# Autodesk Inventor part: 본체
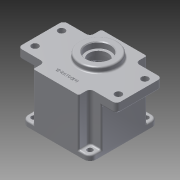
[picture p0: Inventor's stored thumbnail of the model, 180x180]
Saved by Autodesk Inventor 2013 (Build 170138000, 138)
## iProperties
Created: 2015-07
Part Number: 본체
Material: 알루미늄 6061
Document SubType Name: Modeling
Designer: user
Density: 2.71 g/cm^3
Mass: 705.922 g
Surface Area: 675.022 cm^2
Volume: 260.488 cm^3
Author: user
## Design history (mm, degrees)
sketch "스케치1"
  geometry: L1 (-37, 45)-(37, 45); L2 (45, 37)-(45, -37); L3 (37, -45)-(-37, -45); L4 (-45, -37)-(-45, 37); A1 r 8 centre (-37, 37) between (-37, 45) and (-45, 37); A2 r 8 centre (-37, -37) between (-45, -37) and (-37, -45); A3 r 8 centre (37, -37) between (37, -45) and (45, -37); A4 r 8 centre (37, 37) between (45, 37) and (37, 45); 6 further points
  constraints: 8 end point, 8 point on circle, 8 tangent, 6 point on line, 4 centre point, 3 equal radius, 2 midpoint, 2 parallel, 1 horizontal, 1 horizontal alignment, 1 perpendicular, 1 vertical alignment
  dimensions: "d0" = 90 distance of point (45, -45) point (-45, -45); "d1" = 90 distance of point (45, 45) point (45, -45); "d2" = 8 radius of A1
extrude "돌출1" new body sketch "스케치1" distance "d3" = 70; taper "d4" = 0 deg
sketch "스케치2"
  geometry: L1 (37, 45)-(-37, 45) reference; L2 (0, 45)-(0, 30); L3 (0, 30)-(60, 30); L4 (65, 25)-(65, -25); L5 (60, -30)-(-60, -30); L6 (-65, -25)-(-65, 25); L7 (-60, 30)-(0, 30); A1 r 5 centre (-60, 25) between (-60, 30) and (-65, 25); A2 r 5 centre (-60, -25) between (-65, -25) and (-60, -30); A3 r 5 centre (60, -25) between (60, -30) and (65, -25); A4 r 5 centre (60, 25) between (65, 25) and (60, 30); 5 further points
  constraints: 12 end point, 8 point on circle, 8 point on line, 8 tangent, 4 centre point, 4 perpendicular, 3 equal radius, 1 midpoint, 1 parallel
  dimensions: "d5" = 15 distance of L2.start L2.end; "d6" = 65 distance of L2.end point (65, 30); "d7" = 60 distance of point (65, 30) point (65, -30); "d8" = 130 distance of point (65, -30) point (-65, -30); "d9" = 60 distance of point (-65, -30) point (-65, 30); "d10" = 5 radius of A1
extrude "돌출2" join sketch "스케치2" distance "d11" = 12; taper "d12" = 0 deg
sketch "스케치3"
  geometry: L1 (-60, -30)-(-45, -30) reference; L2 (0, 0)-(0, 11); C1 r 25 at (0, 11)
  constraints: 2 end point, 1 centre point, 1 coincident, 1 perpendicular
  dimensions: "d13" = 11 distance of L2.start L2.end; "d14" = 25 radius of C1
extrude "돌출3" join sketch "스케치3" distance "d15" = 7; taper "d16" = 0 deg
sketch "스케치4"
  geometry: C1 r 25 at (0, 0) reference; C2 r 16 at (0, 0); 1 further point
  constraints: 1 centre point, 1 coincident
  dimensions: "d17" = 16 radius of C2
extrude "돌출4" cut sketch "스케치4" distance "d18" = 8; taper "d19" = 0 deg
sketch "스케치5"
  geometry: C1 r 16 at (0, 0) reference; C2 r 12.5 at (0, 0); 1 further point
  constraints: 1 centre point, 1 coincident
  dimensions: "d20" = 12.5 radius of C2
extrude "돌출5" cut sketch "스케치5" distance "d21" = 5; taper "d22" = 0 deg
sketch "스케치6"
  geometry: C1 r 12.5 at (0, 0) reference; C2 r 17.5 at (0, 0); 1 further point
  constraints: 1 centre point, 1 coincident
  dimensions: "d23" = 17.5 radius of C2
extrude "돌출6" cut sketch "스케치6" distance "d24" = 10; taper "d25" = 0 deg
sketch "스케치7"
  geometry: C1 r 40 at (0, 0); 1 further point
  constraints: 1 centre point, 1 coincident
  dimensions: "d26" = 40 radius of C1
extrude "돌출7" cut sketch "스케치7" distance "d27" = 9; taper "d28" = 0 deg
sketch "스케치8"
  geometry: C1 r 40 at (0, 0) reference; C2 r 39 at (0, 0)
  constraints: 1 centre point, 1 coincident
  dimensions: "d29" = 39 radius of C2
extrude "돌출8" cut sketch "스케치8" distance "d30" = 45; taper "d31" = 0 deg
sketch "스케치11"
  geometry: L1 (0, 0)-(0, 11); L2 (0, 0)-(0, -20); C1 r 17.5 at (0, 11) reference; C2 r 39 at (0, 0) reference; C3 r 39 at (0, 0); A1 r 3 centre (12.742, -8.746) between (11.115, -6.225) and (10.493, -10.732); A2 r 3 centre (-12.742, -8.746) between (-10.493, -10.732) and (-11.115, -6.225); A3 r 20.5 centre (0, 11) between (11.115, -6.225) and (-11.115, -6.225); A4 r 14 centre (0, -20) between (-10.493, -10.732) and (10.493, -10.732)
  constraints: 8 point on circle, 5 centre point, 4 end point, 4 tangent, 3 coincident, 1 collinear, 1 concentric, 1 vertical
  dimensions: "d51" = 20 distance of L1.start L2.end; "d53" = 3 radius of A1; "d54" = 3 radius of A2; "d55" = 20.5 radius of A3; "d56" = 14 radius of A4
extrude "돌출11" cut sketch "스케치11" distance "d57" = 7; taper "d58" = 0 deg
sketch "스케치12"
  geometry: L1 (0, 0)-(21.92, 21.92); L2 (0, 0)-(0, 35); C1 r 39 at (0, 0) reference; A1 r 35 centre (0, 0) between (21.763, 27.411) and (27.411, 21.763); A2 r 4 centre (24.749, 24.749) between (21.809, 27.462) and (27.462, 21.809); A3 r 3.5 centre (19.238, 29.836) between (21.762, 27.412) and (21.134, 32.777); A4 r 3.5 centre (29.836, 19.238) between (32.777, 21.134) and (27.412, 21.762); A5 r 39 centre (0, 0) between (32.777, 21.134) and (21.134, 32.777)
  constraints: 18 point on circle, 5 centre point, 5 tangent, 4 end point, 2 coincident, 1 concentric, 1 vertical
  dimensions: "d59" = 35 radius of A1; "d60" = 45 deg angle of L2 L1; "d62" = 4 radius of A2; "d63" = 3.5 radius of A3; "d65" = 3.5 radius of A4; "d66" = 8.23284 distance from line of A4.start L1
extrude "돌출12" join sketch "스케치12" distance "d67" = 52; taper "d68" = 0 deg
sketch "스케치13"
  geometry: C1 r 11 at (0, -20); A1 r 14 centre (0, -20) between (-10.493, -10.732) and (10.493, -10.732) reference; 1 further point
  constraints: 1 centre point, 1 coincident
  dimensions: "d72" = 11 radius of C1
extrude "돌출13" cut sketch "스케치13" distance "d73" = 7; taper "d74" = 0 deg
sketch "스케치14"
  geometry: C1 r 11 at (0, 0) reference; C2 r 9.5 at (0, 0); 1 further point
  constraints: 1 centre point, 1 coincident
  dimensions: "d75" = 9.5 radius of C2
extrude "돌출14" cut sketch "스케치14" distance "d76" = 1; taper "d77" = 0 deg
fillet "모깎기1" dims "d78" = 0.3
fillet "모깎기2" dims "d79" = 2
chamfer "모따기1" distance "d80" = 1; stored, may be unused: second distance "d81" = 2, angle "d82" = 45 deg
fillet "모깎기3" dims "d83" = 2
sketch "스케치15"
  geometry: L1 (37, 45)-(-37, 45) reference; L2 (-45, 37)-(-45, 30) reference; L3 (-60, -30)-(-45, -30) reference; L4 (-30, 45)-(-30, 35); L5 (-35, 30)-(-45, 30); A1 r 8 centre (-37, 37) between (-37, 45) and (-45, 37) reference; A2 r 5 centre (-35, 35) between (-35, 30) and (-30, 35); 2 further points
  constraints: 4 end point, 3 point on line, 2 perpendicular, 2 point on circle, 2 tangent, 1 centre point
  dimensions: "d84" = 15 distance of point (-30, 30) L2.end; "d85" = 5 radius of A2
extrude "돌출15" cut sketch "스케치15" distance "d86" = 63; taper "d87" = 0 deg
sketch "스케치16"
  geometry: L1 (-37, 45)-(-30, 45) reference; L2 (-37, 37)-(-37, 45); L3 (-37, 37)-(-45, 37); C1 r 3.5 at (-37, 37); A1 r 8 centre (-37, 37) between (-37, 45) and (-45, 37) reference; 1 further point
  constraints: 4 end point, 2 perpendicular, 1 centre point, 1 coincident
  dimensions: "d91" = 3.5 radius of C1
extrude "돌출16" cut sketch "스케치16" stored distance "d93" = 63; taper "d94" = 0 deg
sketch "스케치17"
  geometry: L1 (-35, 30)-(-60, 30) reference; L2 (-65, 25)-(-65, -25) reference; L3 (60, 30)-(35, 30) reference; L4 (-55, 30)-(-55, 17.5); L5 (-55, 17.5)-(-65, 17.5); C1 r 4.5 at (-55, 17.5); 1 further point
  constraints: 4 end point, 2 perpendicular, 2 point on line, 1 centre point, 1 coincident
  dimensions: "d98" = 12.5 distance of L4.start L4.end; "d99" = 10 distance of L4.end L5.end; "d100" = 4.5 radius of C1
extrude "돌출17" cut sketch "스케치17" stored distance "d101" = 63; taper "d102" = 0 deg
fillet "모깎기4" dims "d103" = 2
sketch "스케치18"
  geometry: L1 (-30, -45)-(30, -45) reference; L2 (60, 30)-(35, 30) reference; L3 (0, -45)-(0, -30); 2 further points
  constraints: 2 end point, 1 coincident, 1 midpoint, 1 perpendicular, 1 other
  dimensions: "d104" = 15 distance of L3.start L3.end
feature "엠보싱1" sketch "스케치18" dims "d5" = 15, "d6" = 65, "d7" = 60, "d8" = 130, "d9" = 60, "d10" = 5, "d105" = 0.5, "d106" = 0
sketch "스케치19"
  geometry: A1 r 4 centre (-24.749, 24.749) between (-27.462, 21.809) and (-21.809, 27.462) reference
hole "구멍1" sketch "스케치19" at (-24.749, 24.749) diameter "d107" = 3.459; stored, may be unused: countersink angle "d111" = 90 deg, drill point angle "d113" = 118 deg; dims "d108" = 12, "d109" = 4, "d110" = 2, "d112" = 15
fillet "모깎기5" dims "d117" = 2
fillet "모깎기6" dims "d118" = 2
fillet "모깎기7" dims "d119" = 2
fillet "모깎기8" dims "d120" = 2
fillet "모깎기9" dims "d121" = 2
node "솔리드1"
pattern_circular "원형 패턴1" dims angle "d70" = 360 deg
pattern_circular "원형 패턴2" dims angle "d89" = 360 deg
pattern_circular "원형 패턴3" dims angle "d96" = 360 deg
mirror "대칭1"
mirror "대칭2"
pattern_circular "원형 패턴4" dims angle "d115" = 360 deg
other parameters: "d34" = 14, "d50" = 20.5, "d52" = 14
